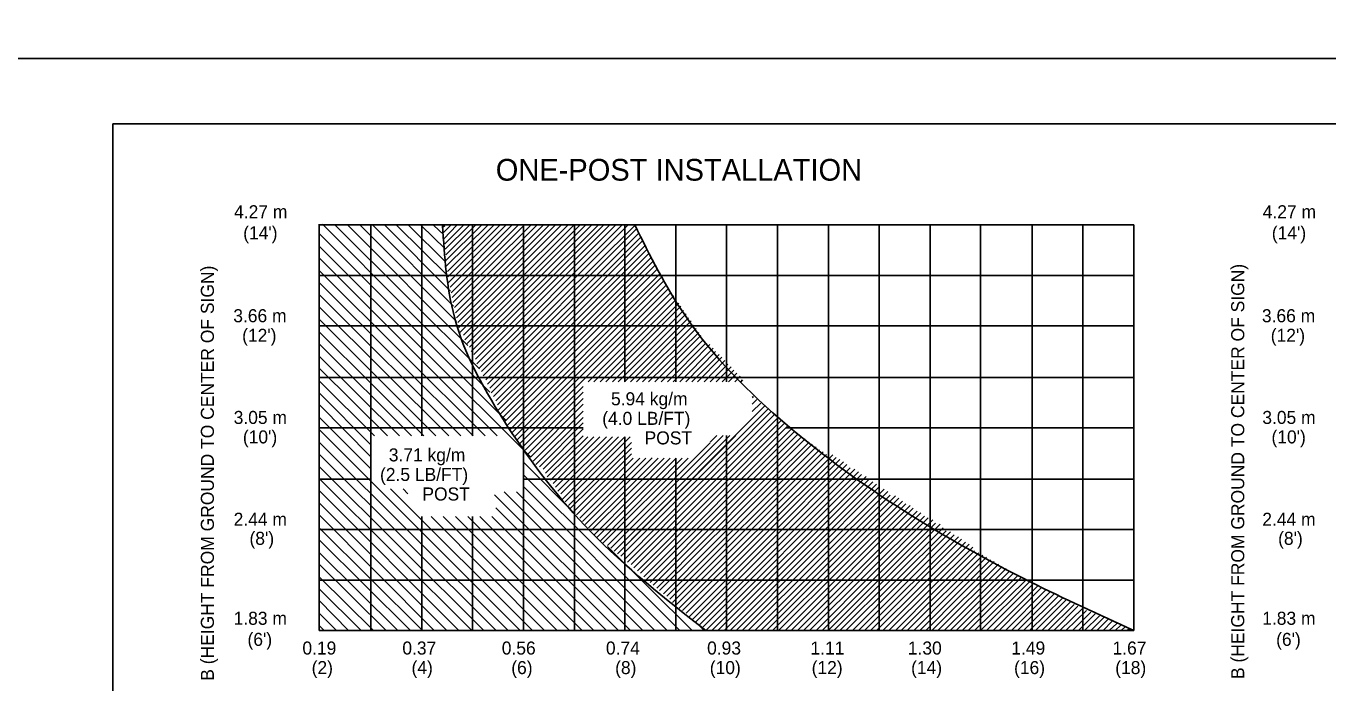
# Model space of a CAD drawing. Extents: x 644358 to 648627, y 294594 to 295782.
# Drawn here: x 645219.3 to 645519, y 295043.9 to 295195.1 of the extents above; entities that cross this region are included whole.
import ezdxf

# ---------------------------------------------------------------- set-up
doc = ezdxf.new("R2010")
doc.units = 0
for name, color, linetype in [('1', 7, 'Continuous'), ('10', 7, 'Continuous'), ('2', 7, 'Continuous'), ('4', 7, 'Continuous'), ('PLT-BNDY', 7, 'Continuous')]:
    doc.layers.add(name, color=color, linetype=linetype)

msp = doc.modelspace()

# ---------------------------------------------------------------- linework, layer by layer
at = {"layer": '1'}
for q in [(646025.31, 295172.63), (645239.31, 294608.63)]:
    msp.add_line((645239.31, 295172.63), q, dxfattribs=at)
at = {"layer": '10'}
for p, q in [((645329.68, 295104.5), (645286.8, 295147.38)), ((645326.09, 295110.83), (645287.55, 295149.5)), ((645323.67, 295116.27), (645290.43, 295149.38)), ((645321.05, 295121.63), (645293.3, 295149.38)), ((645318.43, 295127.13), (645296.18, 295149.38)), ((645317.68, 295130.63), (645299.05, 295149.38)), ((645317.05, 295134.13), (645301.8, 295149.38)), ((645316.43, 295137.63), (645304.68, 295149.25)), ((645315.93, 295140.75), (645307.43, 295149.25)), ((645315.8, 295143.88), (645310.3, 295149.25)), ((645315.43, 295147.13), (645313.18, 295149.25)), ((645315.18, 295148.75), (645315.68, 295149.25)), ((645315.3, 295147.5), (645317.05, 295149.25)), ((645315.55, 295146.25), (645318.43, 295149.25)), ((645315.68, 295145), (645319.93, 295149.25)), ((645315.8, 295143.75), (645321.3, 295149.25)), ((645315.93, 295142.5), (645322.68, 295149.25)), ((645315.93, 295141.13), (645324.05, 295149.25)), ((645316.05, 295139.88), (645325.55, 295149.25)), ((645316.3, 295138.63), (645326.93, 295149.25)), ((645316.43, 295137.38), (645328.3, 295149.25)), ((645316.55, 295136.13), (645329.68, 295149.25)), ((645316.93, 295135), (645331.05, 295149.25)), ((645317.18, 295133.75), (645332.55, 295149.25)), ((645317.43, 295132.63), (645333.93, 295149.25)), ((645317.55, 295131.5), (645335.43, 295149.25)), ((645317.93, 295130.38), (645336.8, 295149.25)), ((645318.18, 295129.13), (645338.3, 295149.25)), ((645318.43, 295128), (645339.68, 295149.25)), ((645318.68, 295126.88), (645341.05, 295149.25)), ((645318.93, 295125.75), (645342.43, 295149.25)), ((645319.18, 295124.63), (645343.93, 295149.25)), ((645320.02, 295123.97), (645345.3, 295149.25)), ((645320.32, 295122.9), (645346.68, 295149.25)), ((645320.84, 295122.04), (645348.05, 295149.25)), ((645321.36, 295121.19), (645349.43, 295149.25)), ((645321.77, 295120.22), (645350.93, 295149.25)), ((645322.43, 295119.51), (645352.3, 295149.38)), ((645322.76, 295118.46), (645353.68, 295149.38)), ((645323.09, 295117.41), (645355.05, 295149.38)), ((645323.73, 295116.43), (645356.55, 295149.38)), ((645324.19, 295115.64), (645357.93, 295149.38)), ((645324.58, 295114.65), (645359.43, 295149.25)), ((645325.13, 295113.71), (645359.8, 295148.38)), ((645325.54, 295112.74), (645360.3, 295147.38)), ((645335.55, 295095.88), (645286.8, 295144.5)), ((645326.1, 295111.8), (645360.8, 295146.5)), ((645326.42, 295110.75), (645361.18, 295145.63)), ((645326.92, 295109.87), (645361.8, 295144.63)), ((645327.77, 295100.78), (645286.8, 295141.75)), ((645327.44, 295108.9), (645362.3, 295143.75)), ((645327.85, 295107.93), (645362.68, 295142.75)), ((645327.93, 295106.63), (645363.18, 295141.88)), ((645328.3, 295105.63), (645363.68, 295141)), ((645325.01, 295100.78), (645286.8, 295138.88)), ((645328.93, 295104.88), (645364.05, 295140)), ((645329.43, 295104), (645364.55, 295139.13)), ((645330.18, 295103.25), (645365.18, 295138.13)), ((645322.26, 295100.78), (645286.8, 295136.13)), ((645330.8, 295102.38), (645365.55, 295137.25)), ((645331.3, 295101.63), (645366.05, 295136.38)), ((645331.93, 295100.75), (645366.68, 295135.5)), ((645319.39, 295100.78), (645286.8, 295133.38)), ((645332.43, 295100), (645367.18, 295134.75)), ((645333.05, 295099.13), (645367.8, 295133.88)), ((645348.7, 295113.28), (645368.43, 295133)), ((645350.01, 295113.28), (645368.93, 295132.13)), ((645316.64, 295100.78), (645286.8, 295130.5)), ((645351.45, 295113.28), (645369.55, 295131.38)), ((645352.76, 295113.28), (645370.05, 295130.63)), ((645354.32, 295113.28), (645370.68, 295129.63)), ((645355.6, 295113.28), (645371.3, 295128.88)), ((645313.64, 295100.78), (645286.8, 295127.63)), ((645357.07, 295113.28), (645371.8, 295128)), ((645358.45, 295113.28), (645372.43, 295127.25)), ((645359.85, 295113.28), (645372.93, 295126.25)), ((645310.88, 295100.78), (645286.8, 295124.75)), ((645361.22, 295113.28), (645373.55, 295125.5)), ((645362.63, 295113.28), (645374.18, 295124.63)), ((645364.07, 295113.28), (645374.68, 295123.88)), ((645365.48, 295113.28), (645375.3, 295123)), ((645308.02, 295100.78), (645286.8, 295122)), ((645366.95, 295113.28), (645375.8, 295122.13)), ((645368.29, 295113.28), (645376.73, 295121.81)), ((645369.82, 295113.28), (645377.52, 295120.97)), ((645371.16, 295113.28), (645378, 295120.21)), ((645305.25, 295100.78), (645286.8, 295119.13)), ((645372.57, 295113.28), (645378.87, 295119.57)), ((645373.9, 295113.28), (645379.46, 295118.92)), ((645375.4, 295113.28), (645380.18, 295118.14)), ((645376.82, 295113.28), (645380.88, 295117.33)), ((645302.5, 295100.78), (645286.8, 295116.38)), ((645378.14, 295113.28), (645381.63, 295116.69)), ((645379.57, 295113.28), (645382.26, 295115.96)), ((645380.99, 295113.28), (645382.9, 295115.25)), ((645382.45, 295113.28), (645383.69, 295114.52)), ((645299.52, 295100.78), (645286.8, 295113.5)), ((645333.68, 295098.25), (645347.57, 295112.15)), ((645383.82, 295113.28), (645384.27, 295113.72)), ((645298.68, 295098.75), (645286.8, 295110.75)), ((645298.68, 295095.97), (645286.8, 295108)), ((645334.18, 295097.5), (645347.57, 295110.85)), ((645334.8, 295096.63), (645347.57, 295109.4)), ((645335.43, 295095.88), (645347.57, 295108.07)), ((645386.5, 295109.61), (645386.79, 295109.9)), ((645386.5, 295108.11), (645387.57, 295109.18)), ((645386.5, 295106.38), (645388.47, 295108.36)), ((645298.68, 295093.25), (645286.8, 295105.13)), ((645336.05, 295095), (645347.57, 295106.53)), ((645336.68, 295094.25), (645347.57, 295105.04)), ((645356.26, 295073.09), (645390.09, 295106.92)), ((645356.98, 295072.31), (645390.8, 295106.31)), ((645357.78, 295071.73), (645391.55, 295105.68)), ((645358.61, 295071.18), (645392.4, 295104.98)), ((645358.65, 295076.98), (645389.29, 295107.62)), ((645333.05, 295056), (645286.8, 295102.25)), ((645337.5, 295093.71), (645347.57, 295103.78)), ((645338.36, 295093.18), (645347.57, 295102.4)), ((645359.21, 295070.41), (645393.16, 295104.36)), ((645360.07, 295069.77), (645393.92, 295103.75)), ((645360.75, 295069.2), (645394.68, 295103.13)), ((645361.56, 295068.39), (645395.43, 295102.38)), ((645362.16, 295067.74), (645396.3, 295101.88)), ((645330.3, 295056), (645286.8, 295099.38)), ((645338.92, 295092.24), (645347.57, 295100.8)), ((645339.29, 295091.36), (645348.6, 295100.58)), ((645340.04, 295090.62), (645350, 295100.58)), ((645340.64, 295089.85), (645351.38, 295100.58)), ((645341.17, 295088.99), (645352.96, 295100.58)), ((645341.72, 295088.05), (645354.35, 295100.58)), ((645342.4, 295087.47), (645355.72, 295100.58)), ((645342.8, 295086.25), (645357.13, 295100.58)), ((645343.43, 295085.63), (645358.38, 295100.58)), ((645344.18, 295084.75), (645358.71, 295099.28)), ((645353.13, 295075.58), (645376.77, 295099.22)), ((645353.9, 295074.98), (645379.81, 295100.89)), ((645354.71, 295074.28), (645381.31, 295100.89)), ((645355.48, 295073.68), (645382.68, 295100.89)), ((645362.99, 295067.07), (645397.05, 295101.25)), ((645363.65, 295066.47), (645397.93, 295100.63)), ((645364.51, 295065.72), (645398.68, 295100.13)), ((645365.16, 295065.23), (645399.55, 295099.38)), ((645366.03, 295064.48), (645400.3, 295098.88)), ((645376.77, 295099.35), (645378.31, 295100.89)), ((645327.55, 295056), (645286.8, 295096.63)), ((645344.68, 295084.13), (645358.71, 295097.97)), ((645345.43, 295083.38), (645358.71, 295096.66)), ((645366.8, 295063.88), (645401.18, 295098.25)), ((645367.49, 295063.19), (645401.93, 295097.63)), ((645368.15, 295062.47), (645402.8, 295097.13)), ((645368.94, 295061.9), (645403.55, 295096.5)), ((645369.67, 295061.12), (645405, 295096.45)), ((645324.68, 295056), (645286.8, 295093.75)), ((645345.68, 295082.88), (645333.8, 295094.75)), ((645346.05, 295082.63), (645359.08, 295095.66)), ((645346.8, 295081.88), (645360.58, 295095.66)), ((645347.43, 295081.13), (645361.96, 295095.66)), ((645348.05, 295080.38), (645363.43, 295095.75)), ((645348.8, 295079.63), (645364.83, 295095.66)), ((645349.43, 295079), (645366.21, 295095.66)), ((645350.18, 295078.13), (645367.58, 295095.66)), ((645350.8, 295077.5), (645368.96, 295095.66)), ((645351.55, 295076.63), (645370.33, 295095.66)), ((645352.05, 295076), (645371.71, 295095.66)), ((645370.4, 295060.6), (645405.77, 295095.84)), ((645371.29, 295059.99), (645406.68, 295095.38)), ((645372.01, 295059.21), (645407.5, 295094.83)), ((645372.55, 295058.38), (645408.24, 295094.2)), ((645373.3, 295057.75), (645409.02, 295093.47)), ((645374.18, 295057.13), (645410.1, 295093.18)), ((645321.93, 295056), (645286.8, 295091)), ((645369.8, 295056), (645333.8, 295091.87)), ((645374.93, 295056.63), (645410.96, 295092.53)), ((645375.8, 295056), (645411.61, 295091.94)), ((645377.18, 295056), (645412.73, 295091.43)), ((645378.55, 295056), (645413.33, 295090.78)), ((645380.05, 295056), (645414.27, 295090.22)), ((645318.93, 295056), (645286.8, 295088.25)), ((645335.93, 295056), (645303.2, 295088.58)), ((645307.18, 295087.5), (645306.1, 295088.58)), ((645358.43, 295056), (645327.18, 295087.25)), ((645361.3, 295056), (645329.36, 295087.95)), ((645364.05, 295056), (645332.23, 295087.95)), ((645366.93, 295056), (645333.8, 295089.13)), ((645381.43, 295056), (645415.1, 295089.67)), ((645382.8, 295056), (645415.8, 295089.13)), ((645384.18, 295056), (645416.87, 295088.56)), ((645385.55, 295056), (645417.69, 295088.02)), ((645387.05, 295056), (645418.24, 295087.19)), ((645388.43, 295056), (645419.43, 295087)), ((645316.18, 295056), (645286.8, 295085.38)), ((645355.68, 295056), (645327.43, 295084.25)), ((645389.8, 295056), (645420.25, 295086.45)), ((645391.18, 295056), (645421.06, 295085.76)), ((645392.55, 295056), (645421.83, 295085.15)), ((645394.05, 295056), (645422.82, 295084.77)), ((645395.43, 295056), (645423.56, 295084.14)), ((645313.3, 295056), (645286.8, 295082.63)), ((645338.68, 295056), (645312.54, 295082.26)), ((645341.55, 295056), (645315.3, 295082.26)), ((645344.43, 295056), (645318.17, 295082.26)), ((645347.3, 295056), (645321.05, 295082.26)), ((645350.05, 295056), (645323.8, 295082.26)), ((645352.93, 295056), (645326.55, 295082.26)), ((645396.93, 295056), (645424.42, 295083.5)), ((645398.3, 295056), (645425.27, 295083.1)), ((645399.68, 295056), (645426.17, 295082.36)), ((645401.18, 295056), (645426.95, 295081.91)), ((645402.55, 295056), (645428.07, 295081.52)), ((645310.55, 295056), (645286.8, 295079.63)), ((645403.93, 295056), (645428.64, 295080.72)), ((645405.3, 295056), (645429.75, 295080.45)), ((645406.68, 295056), (645430.47, 295079.67)), ((645408.05, 295056), (645431.1, 295078.92)), ((645409.55, 295056), (645432.14, 295078.72)), ((645410.93, 295056), (645432.97, 295078.05)), ((645307.8, 295056), (645286.8, 295076.88)), ((645372.68, 295056), (645353.14, 295075.38)), ((645412.3, 295056), (645433.97, 295077.55)), ((645413.68, 295056), (645434.68, 295077.01)), ((645415.05, 295056), (645435.54, 295076.37)), ((645416.55, 295056), (645436.42, 295075.87)), ((645417.93, 295056), (645437.23, 295075.18)), ((645304.93, 295056), (645286.8, 295074)), ((645419.43, 295056), (645437.68, 295074.38)), ((645420.8, 295056), (645438.68, 295073.88)), ((645422.18, 295056), (645439.55, 295073.38)), ((645423.68, 295056), (645440.43, 295072.88)), ((645425.05, 295056), (645441.3, 295072.25)), ((645302.18, 295056), (645286.8, 295071.25)), ((645426.43, 295056), (645442.18, 295071.88)), ((645427.8, 295056), (645443.18, 295071.25)), ((645429.18, 295056), (645444.05, 295070.75)), ((645430.68, 295056), (645444.93, 295070.25)), ((645432.05, 295056), (645445.8, 295069.75)), ((645433.43, 295056), (645446.68, 295069.25)), ((645299.3, 295056), (645286.8, 295068.38)), ((645434.8, 295056), (645447.68, 295068.75)), ((645436.18, 295056), (645448.43, 295068.25)), ((645437.68, 295056), (645449.43, 295067.63)), ((645439.05, 295056), (645450.3, 295067.25)), ((645440.43, 295056), (645451.18, 295066.75)), ((645441.93, 295056), (645452.18, 295066.25)), ((645296.43, 295056), (645286.8, 295065.63)), ((645443.3, 295056), (645453.05, 295065.88)), ((645444.8, 295056), (645454.05, 295065.38)), ((645446.18, 295056), (645455.05, 295064.88)), ((645447.55, 295056), (645455.93, 295064.38)), ((645448.93, 295056), (645456.93, 295063.88)), ((645450.3, 295056), (645457.8, 295063.38)), ((645451.68, 295056), (645458.68, 295063)), ((645293.55, 295056), (645286.8, 295062.88)), ((645290.8, 295056), (645286.8, 295060)), ((645453.18, 295056), (645459.68, 295062.5)), ((645454.55, 295056), (645460.55, 295062)), ((645455.93, 295056), (645461.43, 295061.63)), ((645457.3, 295056), (645462.55, 295061.13)), ((645458.68, 295056), (645463.43, 295060.63)), ((645460.18, 295056), (645464.43, 295060.25)), ((645287.93, 295056), (645286.8, 295057.13)), ((645461.55, 295056), (645465.43, 295059.88)), ((645462.93, 295056), (645466.43, 295059.38)), ((645464.43, 295056), (645467.43, 295059)), ((645465.8, 295056), (645468.43, 295058.63)), ((645467.3, 295056), (645469.3, 295058.13)), ((645468.68, 295056), (645470.43, 295057.63)), ((645470.05, 295056), (645471.3, 295057.25)), ((645375.43, 295056), (645374.55, 295056.88)), ((645471.43, 295056), (645472.3, 295056.88)), ((645472.8, 295056), (645473.3, 295056.38)), ((645474.3, 295056), (645474.3, 295056))]:
    msp.add_line(p, q, dxfattribs=at)
at = {"layer": '2'}
for p, q in [((645286.8, 295056), (645286.8, 295149.5)), ((645474.3, 295149.38), (645286.8, 295149.38)), ((645298.68, 295090.88), (645298.68, 295149.38)), ((645310.43, 295149.38), (645310.43, 295100.78)), ((645322.05, 295149.38), (645322.05, 295100.78)), ((645333.8, 295097), (645333.8, 295149.38)), ((645345.55, 295055.88), (645345.55, 295149.38)), ((645357.18, 295113.28), (645357.18, 295149.38)), ((645368.93, 295149.38), (645368.93, 295113.28)), ((645380.55, 295149.38), (645380.55, 295113.28)), ((645392.3, 295149.38), (645392.3, 295114.25)), ((645404.05, 295056), (645404.05, 295149.38)), ((645415.68, 295055.88), (645415.68, 295149.38)), ((645427.43, 295056), (645427.43, 295149.38)), ((645439.05, 295056), (645439.05, 295149.5)), ((645439.05, 295055.88), (645439.05, 295149.38)), ((645450.93, 295056), (645450.93, 295149.38)), ((645462.55, 295055.88), (645462.55, 295149.38)), ((645474.3, 295056), (645474.3, 295149.38)), ((645474.3, 295137.75), (645287.05, 295137.75)), ((645474.3, 295126.13), (645287.05, 295126.13)), ((645474.3, 295114.25), (645287.05, 295114.25)), ((645392.3, 295114.25), (645392.3, 295056)), ((645287.05, 295102.63), (645347.57, 295102.63)), ((645474.3, 295102.63), (645394.18, 295102.63)), ((645357.18, 295056), (645357.18, 295100.58)), ((645380.55, 295056), (645380.55, 295100.89)), ((645333.8, 295056), (645333.8, 295097.7)), ((645368.93, 295055.88), (645368.93, 295095.66)), ((645286.8, 295090.88), (645298.68, 295090.88)), ((645298.68, 295055.88), (645298.68, 295090.88)), ((645474.3, 295090.88), (645333.8, 295090.88)), ((645310.43, 295056), (645310.43, 295082.26)), ((645322.05, 295056), (645322.05, 295082.26)), ((645474.3, 295079.25), (645286.8, 295079.25)), ((645474.3, 295067.63), (645287.05, 295067.63)), ((645474.3, 295056), (645286.8, 295056))]:
    msp.add_line(p, q, dxfattribs=at)
at = {"layer": '4'}
for points in [[(645375.8, 295056), (645349.18, 295078.88), (645330.18, 295103), (645317.93, 295128.13), (645315.18, 295149.25)], [(645474.3, 295056), (645450.43, 295067.25), (645394.55, 295103.25), (645370.93, 295128.63), (645359.43, 295149.38)]]:
    msp.add_spline(points, degree=3, dxfattribs=at)
at = {"layer": 'PLT-BNDY'}
for points in [[(645199.31, 295781.63), (646040.31, 295781.63), (646040.31, 295187.63), (645199.31, 295187.63)], [(645199.31, 295187.63), (646040.31, 295187.63), (646040.31, 294593.63), (645199.31, 294593.63)]]:
    msp.add_lwpolyline(points, close=True, dxfattribs=at)

# ---------------------------------------------------------------- texts
at = {"layer": '2'}
msp.add_text('ONE-POST INSTALLATION', height=5, dxfattribs=at).set_placement((645327.44, 295159.54))
at = {"layer": '4'}
for s, p in [('4.27 m', (645267.21, 295150.89)), ('4.27 m', (645504, 295150.89)), ("(14')", (645269.3, 295146.05)), ("(14')", (645506.09, 295146.05)), ('3.66 m', (645267.02, 295126.96)), ('3.66 m', (645503.81, 295126.96)), ("(12')", (645269.06, 295122.45)), ("(12')", (645505.84, 295122.45)), ('5.94 kg/m', (645353.97, 295107.84)), ('3.05 m', (645267.11, 295103.55)), ('(4.0 LB/FT)', (645351.95, 295103.34)), ('3.05 m', (645503.9, 295103.55)), ("(10')", (645269.23, 295099.07)), ('POST', (645361.7, 295098.84)), ("(10')", (645506.01, 295099.07)), ('3.71 kg/m', (645302.82, 295094.93)), ('(2.5 LB/FT)', (645300.8, 295090.43)), ('POST', (645310.55, 295085.93)), ('2.44 m', (645267.1, 295080.11)), ('2.44 m', (645503.89, 295080.11)), ("(8')", (645270.75, 295075.73)), ("(8')", (645507.54, 295075.73)), ('1.83 m', (645267.1, 295057.33)), ('1.83 m', (645503.88, 295057.33)), ("(6')", (645270.29, 295052.48)), ("(6')", (645507.08, 295052.48)), ('0.19', (645282.93, 295050.48)), ('0.37', (645305.94, 295050.48)), ('0.56', (645328.82, 295050.48)), ('0.74', (645352.8, 295050.48)), ('0.93', (645376.09, 295050.48)), ('1.11', (645399.89, 295050.48)), ('1.30', (645422.3, 295050.48)), ('1.49', (645446.12, 295050.48)), ('1.67', (645469.42, 295050.48)), ('(2)', (645285.06, 295045.98)), ('(4)', (645308.05, 295045.98)), ('(6)', (645331.01, 295045.98)), ('(8)', (645354.92, 295045.98)), ('(10)', (645376.71, 295045.98)), ('(12)', (645400.16, 295045.98)), ('(14)', (645423.05, 295045.98)), ('(16)', (645446.75, 295045.98)), ('(18)', (645470.04, 295045.98))]:
    msp.add_text(s, height=3, dxfattribs=at).set_placement(p)
for p in [(645262.56, 295043.33), (645499.74, 295043.73)]:
    msp.add_text(' B (HEIGHT FROM GROUND TO CENTER OF SIGN)', height=3.005, rotation=90, dxfattribs=at).set_placement(p)

doc.saveas('drawing.dxf')
